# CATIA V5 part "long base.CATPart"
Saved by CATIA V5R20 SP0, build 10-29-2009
Part number: Part1.1
Bounding box of the stored display mesh (mm): x 0 to 1330, y 0 to 120, z -100 to 160
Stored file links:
  C:\Users\HP\Downloads\Catia Project\Catia Project\long base.CATPart
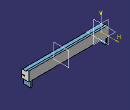
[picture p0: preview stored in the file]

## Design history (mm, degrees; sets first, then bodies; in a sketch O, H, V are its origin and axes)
Body1 (main body)
  Sketch1 on yz-plane, origin (0, 0, 0), H (0, 1, 0), V (0, 0, 1)
    line L1 (0, 0) -> (120, 0)
    line L2 (120, 0) -> (120, 160)
    line L3 (0, 0) -> (0, 125)
    point P3 (0, 135)
    line L4 (10, 135) -> (70, 135)
    point P4 (80, 135)
    line L5 (80, 145) -> (80, 150)
    line L6 (90, 160) -> (120, 160)
    axis line L7 (0, 0) -> (0, 50)
    arc A1 centre (10, 125) radius 10 from (10, 135) to (0, 125) ccw
    arc A2 centre (70, 145) radius 10 from (70, 135) to (80, 145) ccw
    arc A3 centre (90, 150) radius 10 from (80, 150) to (90, 160) cw
    length L1 = 120
    length L2 = 160
    distance P3 P4 = 80
    distance O P3 = 135
    radius A1 = 10
    radius A2 = 10
    radius A3 = 10
    horizontal: L1 H, L4 H, L6 H
    vertical: L2 V, L3 V, L5 V, L7 V
    coincidence: L4 P3, L3 P3, L4 P4, L5 P4
    tangency: A1 L4, A1 L3, A2 L4, A2 L5, A3 L5, A3 L6
  Sketch2 on yz-plane, origin (0, 0, 0), H (0, 1, 0), V (0, 0, 1)
  Pad1: profile Sketch1, direction (1, 0, 0), length 1330
  Sketch3 on end face of Pad1, origin (1330, 0, 0), H (0, 1, 0), V (0, 0, 1)
    axis line L1 (0, 0) -> (0, 50)
    line L2 (0, 50) -> (50, 50)
    line L3 (50, 50) -> (50, 60)
    line L4 (48.8175, 60) -> (0, 60)
    point P4 (0, 60)
    line L5 (0, 60) -> (0, 50)
    length L1 = 50
    length L2 = 50
    length L3 = 10
    vertical: L1 V, L3 V, L5 V
    horizontal: L2 H, L4 H
    coincidence: P4 V
  Pocket1: profile Sketch3, direction (-1, 0, 0), through (limit type 3)
  Sketch4 on face of Pad1 from Sketch1.L1, origin (0, 0, 0), H (1, 0, 0), V (0, -1, 0)
    point P1 (30, 0)
    line L1 (30, 0) -> (50, 0)
    line L2 (50, 0) -> (50, -120)
    line L3 (50, -120) -> (30, -120)
    line L4 (30, -120) -> (30, 0)
    reference projected line E1 (0, 0) -> (1330, 0) from edge [face of Pad1 from Sketch1.L1 | face of Pad1 from Sketch1.L3]
    reference projected line E2 (0, -120) -> (1330, -120) from edge [face of Pad1 from Sketch1.L2 | face of Pad1 from Sketch1.L1]
    reference projected line E3 (0, 0) -> (0, -120) from edge [start face of Pad1 | face of Pad1 from Sketch1.L1]
    distance E3 L4 = 30
    distance L4 L2 = 20
    coincidence: P1 H, L1 E1, L3 E2
    horizontal: L1 H, L3 H
    vertical: L2 V, L4 V
  Pad2: profile Sketch4, direction (0, 0, -1), length 100
  Plane1: type Offset, RefPlane yz-plane, Offset 665
  Mirror1: of Pad2, about Plane1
